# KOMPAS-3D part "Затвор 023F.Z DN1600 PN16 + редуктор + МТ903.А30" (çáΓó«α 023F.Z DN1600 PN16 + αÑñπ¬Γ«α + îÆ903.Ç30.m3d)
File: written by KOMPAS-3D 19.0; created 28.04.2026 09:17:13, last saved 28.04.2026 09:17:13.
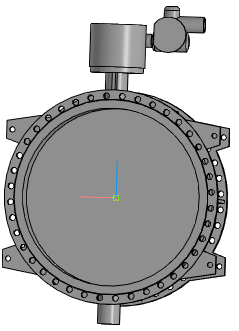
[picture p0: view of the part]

Document properties: Автор: Энергия; Полное имя файла: ..\..\Затвор 023F.Z DN400-DN1600 + редуктор + МТ903\Затвор 023F.Z DN1600 PN16 + редуктор + МТ903.А30.a3d

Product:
- Part/product: Затвор 023F.Z DN1600 PN16 + редуктор + МТ903.А30
    Масса: 4613.98

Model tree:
1. Операция без истории:1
